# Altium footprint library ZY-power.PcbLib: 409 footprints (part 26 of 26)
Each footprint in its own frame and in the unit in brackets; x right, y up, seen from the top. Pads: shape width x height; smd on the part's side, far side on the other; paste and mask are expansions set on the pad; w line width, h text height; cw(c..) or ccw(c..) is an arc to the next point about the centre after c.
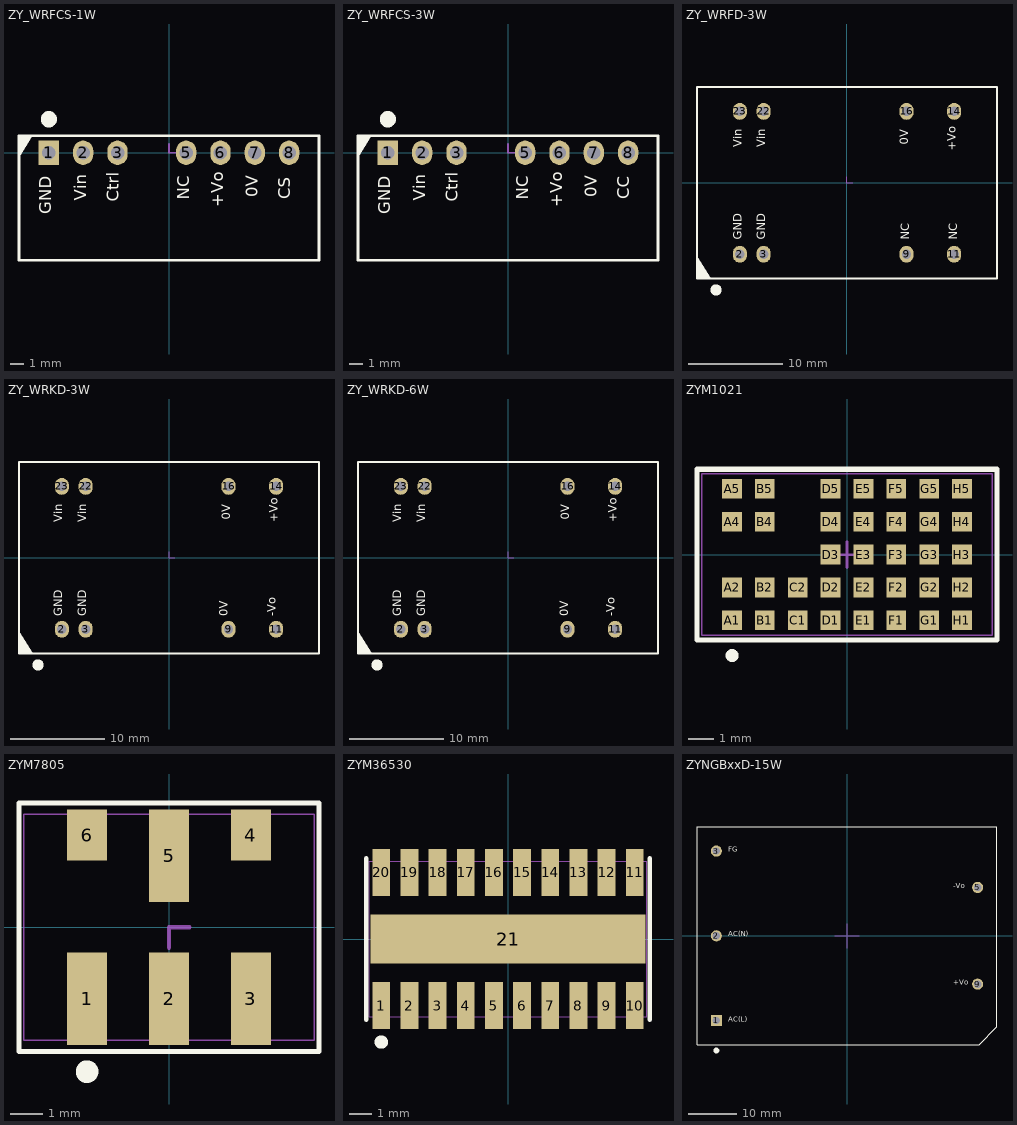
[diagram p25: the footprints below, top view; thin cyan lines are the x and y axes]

## ZY_WRFCS-1W [mm]
height 12.2
pads (7):
  rect 1.5x1.8 hole 1: 1(-8.89,0)
  oval 1.5x1.8 hole 1: 2(-6.35,0) 3(-3.81,0) 5(1.27,0) 6(3.81,0) 7(6.35,0) 8(8.89,0)
Top Overlay:
  circle w1: c-8.89,2.475 r0.1
  region: -11.1,-0.336 -11.1,1.25 -10.106,1.25
  lines w0.2: -11.1,-7.95 11.1,-7.95 11.1,1.25 -11.1,1.25 -11.1,-7.95
  text "GND" at -8.399,-4.572 h1.52
  text "CS" at 9.279,-3.444 h1.52
  text "0V" at 6.866,-3.29 h1.52
  text "+Vo" at 4.326,-4.03 h1.52
  text "NC" at 1.786,-3.501 h1.52
  text "Ctrl" at -3.421,-3.646 h1.52
  text "Vin" at -5.834,-3.562 h1.52
Mechanical 15:
  lines w0.127: 0,0.635 0,0 0.635,0
3D body: height 12.2, standoff 0, extent -11.1,-7.95 11.1,1.25
3D body "zhenjao01.stp": height 8.36, standoff -4.08, extent 5.65,-1.48 7.05,0.12
3D body "zhenjao01.stp": height 8.36, standoff -4.08, extent 3.11,-1.48 4.51,0.12
3D body "zhenjao01.stp": height 8.36, standoff -4.08, extent 0.57,-1.48 1.97,0.12
3D body "zhenjao01.stp": height 8.36, standoff -4.08, extent -4.51,-1.48 -3.11,0.12
3D body "zhenjao01.stp": height 8.36, standoff -4.08, extent -7.05,-1.48 -5.65,0.12
3D body "zhenjao01.stp": height 8.36, standoff -4.08, extent -9.59,-1.48 -8.19,0.12
3D body "zhenjao01.stp": height 8.36, standoff -4.08, extent 8.19,-1.48 9.59,0.12

## ZY_WRFCS-3W [mm]
height 12.2
pads (7):
  rect 1.5x1.8 hole 1: 1(-8.89,0)
  oval 1.5x1.8 hole 1: 2(-6.35,0) 3(-3.81,0) 5(1.27,0) 6(3.81,0) 7(6.35,0) 8(8.89,0)
Top Overlay:
  circle w1: c-8.89,2.475 r0.1
  region: -11.1,-0.336 -11.1,1.25 -10.106,1.25
  lines w0.2: -11.1,-7.95 -11.1,1.25 11.1,1.25 11.1,-7.95 -11.1,-7.95
  text "Vin" at -5.834,-3.562 h1.52
  text "Ctrl" at -3.421,-3.646 h1.52
  text "NC" at 1.786,-3.501 h1.52
  text "+Vo" at 4.326,-4.03 h1.52
  text "0V" at 6.866,-3.29 h1.52
  text "CC" at 9.279,-3.444 h1.52
  text "GND" at -8.399,-4.572 h1.52
Mechanical 15:
  lines w0.127: 0,0.635 0,0 0.635,0
3D body "zhenjao01.stp": height 8.36, standoff -4.08, extent 8.19,-1.48 9.59,0.12
3D body "zhenjao01.stp": height 8.36, standoff -4.08, extent -9.59,-1.48 -8.19,0.12
3D body "zhenjao01.stp": height 8.36, standoff -4.08, extent -7.05,-1.48 -5.65,0.12
3D body "zhenjao01.stp": height 8.36, standoff -4.08, extent -4.51,-1.48 -3.11,0.12
3D body "zhenjao01.stp": height 8.36, standoff -4.08, extent 0.57,-1.48 1.97,0.12
3D body "zhenjao01.stp": height 8.36, standoff -4.08, extent 3.11,-1.48 4.51,0.12
3D body "zhenjao01.stp": height 8.36, standoff -4.08, extent 5.65,-1.48 7.05,0.12
3D body: height 12.2, standoff 0, extent -11.1,-7.95 11.1,1.25

## ZY_WRFD-3W [mm]
height 10.2
pads (8):
  oval 1.5x1.8 hole 1: 2(-11.43,-7.62) 3(-8.89,-7.62) 9(6.35,-7.62) 11(11.43,-7.62) 14(11.43,7.62) 16(6.35,7.62) 22(-8.89,7.62) 23(-11.43,7.62)
Top Overlay:
  circle w1: c-13.97,-11.425 r0.1
  region: -16,-7.87 -16,-10.2 -14.54,-10.2
  lines w0.2: -16,-10.2 16,-10.2 16,10.2 -16,10.2 -16,-10.2
  text "NC" at 6.985,-6.096 h1.52
  text "0V" at 6.858,4.064 h1.52
  text "+Vo" at 11.938,3.429 h1.52
  text "NC" at 12.065,-6.096 h1.52
  text "Vin" at -8.382,3.81 h1.52
  text "Vin" at -10.922,3.81 h1.52
  text "GND" at -8.382,-6.096 h1.52
  text "GND" at -10.922,-6.096 h1.52
Mechanical 15:
  lines w0.127: 0,0.635 0,0 0.635,0
3D body: height 11, standoff 0, extent -16,-10.2 16,10.2
3D body "zhen01.stp": height 6.09, standoff -4.41, extent -11.68,7.37 -11.18,7.87
3D body "zhen01.stp": height 6.09, standoff -4.41, extent -9.14,7.37 -8.64,7.87
3D body "zhen01.stp": height 6.09, standoff -4.41, extent 6.1,7.37 6.6,7.87
3D body "zhen01.stp": height 6.09, standoff -4.41, extent 11.18,7.37 11.68,7.87
3D body "zhen01.stp": height 6.09, standoff -4.41, extent 11.18,-7.87 11.68,-7.37
3D body "zhen01.stp": height 6.09, standoff -4.41, extent -11.68,-7.87 -11.18,-7.37
3D body "zhen01.stp": height 6.09, standoff -4.41, extent -9.14,-7.87 -8.64,-7.37
3D body "zhen01.stp": height 6.09, standoff -4.41, extent 6.1,-7.87 6.6,-7.37

## ZY_WRKD-3W [mm]
height 10.2
pads (8):
  oval 1.5x1.8 hole 1: 2(-11.43,-7.62) 3(-8.89,-7.62) 9(6.35,-7.62) 11(11.43,-7.62) 14(11.43,7.62) 16(6.35,7.62) 22(-8.89,7.62) 23(-11.43,7.62)
Top Overlay:
  circle w1: c-13.97,-11.425 r0.1
  region: -16,-7.87 -16,-10.2 -14.54,-10.2
  lines w0.2: -16,-10.2 -16,10.2 16,10.2 16,-10.2 -16,-10.2
  text "0V" at 6.604,-6.223 h1.52
  text "GND" at -11.049,-6.223 h1.52
  text "GND" at -8.509,-6.223 h1.52
  text "Vin" at -11.049,3.81 h1.52
  text "Vin" at -8.509,3.81 h1.52
  text "-Vo" at 11.684,-6.223 h1.52
  text "+Vo" at 11.938,3.81 h1.52
  text "0V" at 6.858,4.064 h1.52
Mechanical 15:
  lines w0.127: 0,0.635 0,0 0.635,0

## ZY_WRKD-6W [mm]
height 10.5
pads (8):
  oval 1.5x1.8 hole 1: 2(-11.43,-7.62) 3(-8.89,-7.62) 9(6.35,-7.62) 11(11.43,-7.62) 14(11.43,7.62) 16(6.35,7.62) 22(-8.89,7.62) 23(-11.43,7.62)
Top Overlay:
  circle w1: c-13.97,-11.425 r0.1
  region: -16,-7.87 -16,-10.2 -14.54,-10.2
  lines w0.2: -16,-10.2 -16,10.2 16,10.2 16,-10.2 -16,-10.2
  text "0V" at 6.731,-6.223 h1.52
  text "GND" at -11.049,-6.223 h1.52
  text "GND" at -8.509,-6.223 h1.52
  text "Vin" at -11.049,3.81 h1.52
  text "Vin" at -8.509,3.81 h1.52
  text "-Vo" at 11.684,-6.223 h1.52
  text "+Vo" at 11.938,3.81 h1.52
  text "0V" at 6.858,4.064 h1.52
Mechanical 15:
  lines w0.127: 0,0.635 0,0 0.635,0

## ZYM1021 [mil]
height 118.11
pads (35):
  rect 30x30 smd mask+2: A1(-175,-100) A2(-175,-50) A4(-175,50) A5(-175,100) B1(-125,-100) B2(-125,-50) B4(-125,50) B5(-125,100) C1(-75,-100) C2(-75,-50) D1(-25,-100) D2(-25,-50) D3(-25,0) D4(-25,50) D5(-25,100) E1(25,-100) E2(25,-50) E3(25,0) E4(25,50) E5(25,100) F1(75,-100) F2(75,-50) F3(75,0) F4(75,50) F5(75,100) G1(125,-100) G2(125,-50) G3(125,0) G4(125,50) G5(125,100) H1(175,-100) H2(175,-50) H3(175,0) H4(175,50) H5(175,100)
Top Overlay:
  circle w9.84: c-175,-153.72 r4.92
  lines w7.87: -228.35,-129.92 228.35,-129.92 228.35,129.92 -228.35,129.92 -228.35,-129.92
Mechanical 13:
  lines w2: -221.46,-123.03 -221.46,123.03 221.46,123.03 221.46,-123.03 -221.46,-123.03
Mechanical 15:
  lines w3.94: -19.68,0 19.69,0 ; 0,-19.68 0,19.69

## ZYM7805 [mm]
height 3
pads (12):
  rect 1.25x2.87 smd mask+0.051: 1(-2.54,-2.215) 2(0,-2.215) 3(2.54,-2.215) 5(0,2.215)
  rect 1.25x1.58 smd mask+0.051: 4(2.54,2.86) 6(-2.54,2.86)
  rect 1.05x2.42 on Mech15 paste-2 mask-2: ""(-2.54,-2.09) ""(0,-2.09) ""(0,2.09) ""(2.54,-2.09)
  rect 1.05x1.12 on Mech15 paste-2 mask-2: ""(-2.54,2.74) ""(2.54,2.74)
Top Overlay:
  circle w0.5: c-2.54,-4.476 r0.1
  lines w0.152: -4.65,-3.85 4.65,-3.85 4.65,3.85 -4.65,3.85 -4.65,-3.85
Mechanical 15:
  lines w0.051: -4.5,-3.5 -4.5,3.5 4.5,3.5 4.5,-3.5 -4.5,-3.5
  lines w0.127: 0,-0.635 0,0 0.635,0

## ZYM36530 [mm]
height 3
pads (21):
  rect 0.8x2.1 smd: 1(-5.715,-3) 2(-4.445,-3) 3(-3.175,-3) 4(-1.905,-3) 5(-0.635,-3) 6(0.635,-3) 7(1.905,-3) 8(3.175,-3) 9(4.445,-3) 10(5.715,-3) 11(5.715,3) 12(4.445,3) 13(3.175,3) 14(1.905,3) 15(0.635,3) 16(-0.635,3) 17(-1.905,3) 18(-3.175,3) 19(-4.445,3) 20(-5.715,3)
  rect 12.4x2.2 smd: 21(0,0)
Top Overlay:
  circle w0.4: c-5.715,-4.649 r0.1
  lines w0.2: -6.4,-3.65 -6.4,3.65 ; 6.4,-3.65 6.4,3.65
Mechanical 13:
  lines w0.05: -6.25,-3.5 6.25,-3.5 6.25,3.5 -6.25,3.5 -6.25,-3.5
Mechanical 15:
  lines w0.05: 0,-0.635 0,0 0.635,0

## ZYNGBxxD-15W [mm] "120426 修改 by kong"
height 22.5
pads (5):
  rect 2.3x2.3 hole 1.5: 1(-27,-17.5)
  round 2.3 hole 1.5: 2(-27,0) 3(-27,17.5) 5(27,10) 9(27,-10)
Top Overlay:
  circle w1: c-27,-23.725 r0.1
  lines w0.2: -31,-22.5 -31,22.5 31,22.5 31,-18.825 27.325,-22.5 -31,-22.5
  text "-Vo" at 21.92,9.424 h1.78
  text "+Vo" at 21.92,-10.515 h1.78
  text "FG" at -24.587,16.917 h1.78
  text "AC(N)" at -24.587,-0.482 h1.78
  text "AC(L)" at -24.587,-18.135 h1.78
Mechanical 15:
  lines w0.152: -2.54,0 2.54,0 ; 0,-2.54 0,2.54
